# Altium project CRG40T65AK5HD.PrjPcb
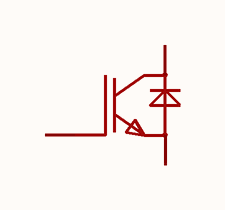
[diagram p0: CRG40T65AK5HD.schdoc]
1 sheet, 1 parts. Net scope: global (net labels, ports and power ports of the same name join across sheets).

## Sheet CRG40T65AK5HD.schdoc
size 127 x 101 mm

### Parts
U?  crg40t65ak5hd  [TO-247-3_L15.9-W5.0-P5.44-L]  (value not drawn)

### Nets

Not connected (* = marked no-connect by the designer): U? 1(G) 2(C) 3(E)

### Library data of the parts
U? = crg40t65ak5hd: IGBT类型:FS(场截止);耗散功率(Pd):250W;集射极击穿电压(Vces):650V;集电极电流(Ic):40A;; Manufacturer: CRMICRO(华润微); AddInBom: yes; ModelId: 06d11a66e67643458860efec572770e6; ModelTransform: 625.983,196.85,0,0,0,0,0,5.906,-196.85; Pd - Power Dissipation: 250W; Collector-Emitter Breakdown Voltage (Vces): 650V; Current - Collector(Ic): 40A; Current - Collector Pulsed (Icm): 160A; Vce Saturation(VCE(sat)): 1.65V; Gate-Emitter Threshold Voltage (Vge(th)@Ic): 3.5V@250uA; Gate Charge(Qg): 97nC@15V; Input Capacitance(Cies): 2.805nF; Output Capacitance(Coes): 119pF; Reverse Transfer Capacitance (Cres): 17pF; Td(on): 54ns; Td(off): 200ns; Turn-On Energy (Eon): 1.8mJ; Switching Energy(Eoff): 720uJ; Reverse Recovery Time(trr): 48ns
